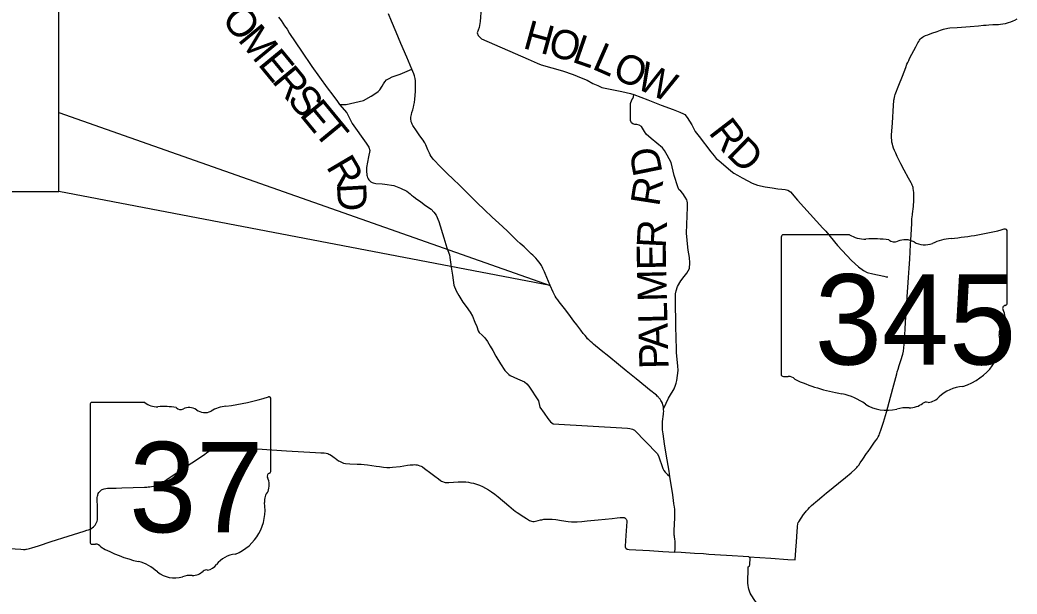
# Model space of a CAD drawing. Extents: x 1761803 to 2441803, y 509895 to 949895.
# Drawn here: x 2027446 to 2058182, y 720477 to 738164 of the extents above; entities that cross this region are included whole.
import ezdxf

# ---------------------------------------------------------------- set-up
doc = ezdxf.new("R2010")
doc.units = 0
for name, color, linetype in [('GM_X_County_Road', 7, 'Continuous'), ('GM_X_Minor_Lake', 7, 'Continuous'), ('GM_X_State_Location', 7, 'Continuous'), ('GM_X_Township_Road', 7, 'Continuous')]:
    doc.layers.add(name, color=color, linetype=linetype)

msp = doc.modelspace()

# ---------------------------------------------------------------- linework, layer by layer
at = {"layer": 'GM_X_County_Road'}
for points in [[(2041730, 739361), (2041632, 738116), (2041605, 737932), (2041538, 737768), (2041570, 737688), (2041675, 737580), (2043109, 736954), (2043389, 736833), (2043512, 736786), (2044171, 736592), (2044504, 736485), (2044750, 736378), (2044933, 736309), (2045105, 736208), (2045256, 736150), (2045388, 736083), (2046003, 735955), (2046269, 735900), (2046370, 735869), (2046797, 735702), (2047214, 735544), (2047581, 735403), (2047783, 735328), (2047898, 735274)], [(2035414, 738255), (2035501, 738148), (2035596, 737984), (2035680, 737882), (2035755, 737745), (2036124, 737202), (2036443, 736733), (2036915, 736075), (2037087, 735846), (2037232, 735654), (2037300, 735560)], [(2037300, 735560), (2037500, 735564), (2038033, 735683), (2038271, 735819), (2038358, 735867), (2038492, 735956), (2038538, 736014), (2038608, 736125), (2038650, 736200), (2038691, 736258), (2038745, 736316), (2038826, 736365), (2038923, 736408), (2039167, 736492), (2039528, 736644)], [(2047528, 726662), (2047552, 726701), (2047608, 726798), (2047658, 726912), (2047675, 726970), (2047691, 727054), (2047718, 727214), (2047732, 727362), (2047729, 727509), (2047688, 727904), (2047687, 728022), (2047668, 728719), (2047652, 729556), (2047656, 729722), (2047671, 729814), (2047713, 729950), (2047820, 730126), (2047916, 730265), (2047998, 730359), (2048085, 730509), (2048096, 730681), (2048086, 730841), (2048041, 731068), (2048030, 731166), (2047995, 731598), (2048027, 732395), (2048020, 732532), (2048012, 732586), (2048000, 732624), (2047951, 732707), (2047875, 732819), (2047818, 732889), (2047758, 732944), (2047728, 733028), (2047612, 733371), (2047523, 733775), (2047396, 733996), (2047319, 734143), (2047254, 734222), (2047080, 734371), (2046900, 734516), (2046748, 734641), (2046693, 734723), (2046601, 734886), (2046529, 734927), (2046462, 734942), (2046404, 734944), (2046334, 734959), (2046296, 734992), (2046267, 735067), (2046264, 735161), (2046271, 735595), (2046306, 735707), (2046334, 735749), (2046356, 735799), (2046370, 735869)], [(2037300, 735560), (2037521, 735302), (2037689, 734977), (2038118, 734365), (2038199, 734240), (2038227, 734139), (2038190, 733945), (2038126, 733614), (2038124, 733519), (2038135, 733384), (2038144, 733355), (2038156, 733314), (2038175, 733274), (2038199, 733237), (2038266, 733182), (2038304, 733161), (2038338, 733142), (2038375, 733131), (2038420, 733127), (2038613, 733118), (2038698, 733108), (2038972, 733064), (2039175, 732984), (2039369, 732885), (2039471, 732804), (2039517, 732767)], [(2047898, 735274), (2047899, 735273), (2047937, 735255), (2048014, 735157), (2048161, 734930), (2048258, 734730), (2048381, 734569), (2048743, 734101), (2048850, 733975), (2048910, 733900), (2048985, 733836), (2049356, 733521), (2049453, 733444), (2049569, 733378), (2049708, 733297), (2049880, 733206), (2050022, 733138), (2050183, 733071), (2050415, 733026), (2050633, 732996), (2050812, 732965), (2050936, 732952), (2051030, 732936), (2051116, 732924), (2051198, 732871), (2051414, 732616), (2052199, 731751), (2052283, 731655), (2052643, 731215), (2053074, 730757), (2053293, 730554), (2053444, 730445), (2053564, 730383), (2053737, 730338), (2054075, 730267), (2054152, 730255), (2054203, 730248)], [(2039517, 732767), (2039573, 732727), (2039640, 732675), (2039802, 732558), (2039951, 732451), (2040118, 732334), (2040208, 732239), (2040278, 732147), (2040363, 731950), (2040517, 731456), (2040602, 731142), (2040692, 730923), (2040737, 730547), (2040775, 730301), (2040820, 729991), (2040897, 729817), (2040970, 729671), (2041102, 729467), (2041204, 729336), (2041328, 729160), (2041396, 729040), (2041466, 728852), (2041531, 728715), (2041572, 728587), (2041598, 728534), (2041691, 728450), (2041778, 728366), (2041861, 728259), (2041945, 728118), (2042023, 727976), (2042119, 727808), (2042255, 727571), (2042396, 727363), (2042474, 727279), (2042516, 727246)], [(2042516, 727246), (2042555, 727215), (2042784, 727112), (2043001, 727010), (2043067, 726952), (2043128, 726877), (2043434, 726429), (2043473, 726239), (2043610, 726045), (2043723, 725884), (2043800, 725784), (2043882, 725723), (2046170, 725587), (2046245, 725580), (2046289, 725568), (2046333, 725553), (2046385, 725524), (2047089, 724802), (2047129, 724735), (2047261, 724343), (2047299, 724285), (2047332, 724227), (2047410, 724158), (2047483, 724097)], [(2047287, 726186), (2047362, 726359), (2047437, 726512), (2047528, 726662)]]:
    msp.add_lwpolyline(points, dxfattribs=at)
at = {"layer": 'GM_X_Minor_Lake'}
for points in [[(2047625, 722629), (2047634, 722826), (2047637, 722941), (2047635, 723003), (2047629, 723085), (2047622, 723160), (2047616, 723206), (2047606, 723268), (2047594, 723360), (2047567, 723533), (2047483, 724097), (2047457, 724261), (2047371, 724790), (2047319, 725107), (2047270, 725411), (2047254, 725536), (2047252, 725577), (2047250, 725621), (2047250, 725662), (2047250, 725705), (2047252, 725745), (2047256, 725793), (2047283, 726023), (2047286, 726058), (2047289, 726105), (2047288, 726160), (2047287, 726186), (2047280, 726247), (2047265, 726311), (2047248, 726356), (2047222, 726412), (2047202, 726445), (2047177, 726482), (2047153, 726511), (2047133, 726535), (2047115, 726552), (2047092, 726575), (2047063, 726600), (2046854, 726769), (2046733, 726869), (2046445, 727103), (2046136, 727355), (2045901, 727547), (2045599, 727794), (2045363, 727985), (2045130, 728172), (2045080, 728215), (2045033, 728258), (2044986, 728304), (2044946, 728345), (2044906, 728388), (2044865, 728438), (2044811, 728505), (2044738, 728603), (2044610, 728773), (2044521, 728889), (2044416, 729028), (2044330, 729142), (2044229, 729272), (2044150, 729375), (2044071, 729477), (2044025, 729540), (2043980, 729604), (2043945, 729659), (2043910, 729721), (2043881, 729780), (2043794, 729983), (2043691, 730230), (2043641, 730352), (2043619, 730404), (2043600, 730445), (2043569, 730510), (2043545, 730554), (2043522, 730595), (2043502, 730628), (2043477, 730665), (2043444, 730711), (2043401, 730763), (2043347, 730826), (2043306, 730867), (2043259, 730913), (2043206, 730963), (2043147, 731020), (2042985, 731170), (2042870, 731278), (2042778, 731364), (2042461, 731663), (2042206, 731901), (2042004, 732091), (2041770, 732311), (2041542, 732532), (2041315, 732755), (2041179, 732889), (2040981, 733083), (2040812, 733249), (2040610, 733447), (2040379, 733672), (2040222, 733831), (2040189, 733868), (2040159, 733906), (2040123, 733956), (2040094, 734008), (2040068, 734058), (2040039, 734118), (2040020, 734166), (2040001, 734214), (2039982, 734261), (2039955, 734320), (2039924, 734375), (2039902, 734411), (2039871, 734458), (2039775, 734594), (2039687, 734720), (2039647, 734778), (2039577, 734881), (2039556, 734915), (2039538, 734951), (2039523, 734986), (2039510, 735024), (2039501, 735059), (2039495, 735102), (2039495, 735137), (2039498, 735173), (2039505, 735212), (2039513, 735253), (2039528, 735308), (2039554, 735400), (2039576, 735481), (2039591, 735543), (2039604, 735619), (2039618, 735719), (2039636, 735963), (2039644, 736105), (2039644, 736157), (2039643, 736223), (2039638, 736288), (2039625, 736360), (2039605, 736441), (2039583, 736506), (2039556, 736575), (2039528, 736644), (2039369, 737021), (2039192, 737442), (2039046, 737789), (2038902, 738130), (2038807, 738356)], [(2054958, 732163), (2054962, 732196), (2054988, 732419), (2054993, 732486), (2054997, 732541), (2055002, 732647), (2055002, 732748), (2055000, 732849), (2054995, 732913), (2054985, 732971), (2054978, 733002), (2054967, 733035), (2054952, 733075), (2054936, 733109), (2054920, 733144), (2054837, 733289), (2054700, 733541), (2054600, 733728), (2054489, 733962), (2054441, 734065), (2054407, 734139), (2054378, 734211), (2054353, 734284), (2054338, 734333), (2054326, 734404), (2054318, 734469), (2054316, 734523), (2054316, 734611), (2054339, 734999), (2054371, 735525), (2054372, 735576), (2054381, 735633), (2054386, 735688), (2054390, 735727), (2054401, 735779), (2054413, 735830), (2054426, 735871), (2054537, 736159), (2054652, 736435), (2054752, 736703), (2054788, 736800), (2054813, 736858), (2054843, 736918), (2054869, 736975), (2054944, 737113), (2055063, 737334), (2055123, 737456), (2055151, 737504), (2055176, 737543), (2055197, 737571), (2055230, 737604), (2055267, 737634), (2055301, 737656), (2055364, 737684), (2055436, 737710), (2055560, 737755), (2055718, 737809), (2055823, 737846), (2055882, 737868), (2055918, 737880), (2055957, 737891), (2056004, 737903), (2056044, 737909), (2056111, 737919), (2056334, 737934), (2056739, 737966), (2056997, 737987), (2057144, 737999), (2057226, 738007), (2057314, 738014), (2057440, 738021), (2057550, 738027), (2057612, 738029), (2057676, 738032), (2057747, 738042), (2057822, 738056), (2057920, 738081), (2057992, 738107), (2058059, 738134), (2058113, 738160), (2058182, 738196)], [(2054779, 729374), (2054782, 729430), (2054797, 729641), (2054815, 729921), (2054833, 730225), (2054856, 730521), (2054877, 730797), (2054901, 731244), (2054920, 731542), (2054935, 731893), (2054940, 731971), (2054943, 732041), (2054958, 732163)], [(2053927, 725370), (2053927, 725371), (2053947, 725418), (2053994, 725552), (2054064, 725770), (2054161, 726081), (2054244, 726385), (2054353, 726807), (2054474, 727264), (2054489, 727320), (2054514, 727403), (2054549, 727515), (2054616, 727729), (2054640, 727804), (2054657, 727871), (2054679, 727961), (2054695, 728059), (2054705, 728165), (2054710, 728263), (2054746, 728848), (2054779, 729374)], [(2053544, 724802), (2053592, 724872), (2053660, 724970), (2053770, 725125), (2053823, 725199), (2053869, 725263), (2053902, 725320), (2053927, 725370)], [(2027648, 721857), (2027699, 721866), (2027736, 721876), (2027809, 721898), (2028014, 721963), (2028408, 722091), (2028937, 722259), (2029423, 722415), (2029507, 722440), (2029556, 722457), (2029607, 722476), (2029637, 722491), (2029673, 722513), (2029713, 722547), (2029743, 722578), (2029754, 722590), (2029762, 722601), (2029787, 722640), (2029807, 722680), (2029822, 722724), (2029832, 722765), (2029839, 722828), (2029839, 722910), (2029833, 723172), (2029831, 723376), (2029831, 723455), (2029836, 723493), (2029842, 723528), (2029860, 723572), (2029876, 723603), (2029894, 723627), (2029917, 723651), (2029940, 723672), (2029963, 723689), (2029985, 723701), (2030010, 723713), (2030042, 723723), (2030089, 723731), (2030149, 723735), (2030408, 723744), (2030586, 723751), (2031287, 723772), (2031355, 723773), (2031402, 723777), (2031451, 723782), (2031504, 723789), (2031568, 723802), (2031629, 723819), (2031694, 723843), (2031760, 723874), (2031836, 723915), (2031969, 724003), (2032385, 724280), (2033102, 724759), (2033240, 724854), (2033294, 724890), (2033348, 724923), (2033396, 724950), (2033448, 724973), (2033498, 724994), (2033557, 725011), (2033596, 725020), (2033637, 725027), (2033680, 725031), (2033718, 725033), (2033770, 725031), (2033857, 725025), (2034370, 724983), (2034757, 724952), (2035665, 724887), (2036558, 724840), (2036724, 724831), (2036782, 724828), (2036822, 724824), (2036886, 724813), (2036932, 724802), (2036965, 724790), (2037000, 724774), (2037046, 724748), (2037095, 724716), (2037135, 724687), (2037162, 724666), (2037270, 724586), (2037297, 724568), (2037338, 724547), (2037380, 724526), (2037421, 724513), (2037481, 724501), (2037616, 724492), (2037843, 724481), (2037965, 724474), (2038056, 724467), (2038155, 724456), (2038297, 724438), (2038429, 724419), (2038528, 724405), (2038648, 724389), (2038756, 724380), (2038849, 724377), (2038931, 724382), (2039170, 724411), (2039391, 724443), (2039472, 724454), (2039518, 724460), (2039570, 724463), (2039610, 724464), (2039649, 724462), (2039689, 724455), (2039721, 724449), (2039774, 724432), (2039816, 724413), (2039853, 724393), (2039918, 724350), (2040111, 724203), (2040236, 724106), (2040347, 724022), (2040411, 723976), (2040439, 723959), (2040476, 723941), (2040518, 723926), (2040552, 723918), (2040578, 723914), (2040600, 723913), (2040663, 723913), (2040959, 723931), (2041076, 723937), (2041136, 723936), (2041195, 723931), (2041270, 723922), (2041344, 723908), (2041431, 723888), (2041521, 723863), (2041609, 723832), (2041701, 723789), (2041795, 723741), (2041890, 723686), (2041984, 723628), (2042082, 723558), (2042184, 723474), (2042513, 723194), (2042660, 723071), (2042708, 723033), (2042769, 722992), (2042974, 722857), (2043059, 722802), (2043119, 722762), (2043150, 722743), (2043185, 722730), (2043219, 722720), (2043259, 722715), (2043295, 722714), (2043337, 722719), (2043421, 722740), (2043496, 722760), (2043530, 722768), (2043595, 722780), (2043610, 722782)], [(2053425, 724628), (2053544, 724802)], [(2053240, 724372), (2053243, 724376), (2053268, 724404), (2053302, 724450), (2053349, 724516), (2053425, 724628)], [(2051907, 723256), (2051979, 723318), (2052028, 723359), (2052163, 723474), (2052312, 723594), (2052450, 723705), (2052516, 723758), (2052675, 723890), (2052890, 724067), (2053069, 724216), (2053193, 724324), (2053215, 724347), (2053240, 724372)], [(2051423, 722629), (2051427, 722643), (2051439, 722681), (2051451, 722705), (2051601, 722923), (2051657, 722999), (2051685, 723034), (2051713, 723066), (2051742, 723097), (2051785, 723144), (2051846, 723200), (2051907, 723256)], [(2043610, 722782), (2043645, 722786), (2043710, 722789), (2043795, 722787), (2043856, 722782), (2043965, 722769), (2044142, 722745), (2044345, 722717), (2044449, 722705), (2044528, 722700), (2044625, 722699), (2044763, 722709), (2044929, 722728), (2045270, 722763), (2045706, 722807), (2045852, 722822), (2045952, 722832), (2045998, 722835), (2046031, 722836), (2046033, 722836)], [(2046033, 722836), (2046051, 722835), (2046065, 722833), (2046075, 722831), (2046085, 722827), (2046102, 722820), (2046117, 722809), (2046127, 722797), (2046136, 722783), (2046143, 722766), (2046151, 722741), (2046152, 722716), (2046143, 722567), (2046126, 722276), (2046105, 721954), (2046106, 721927), (2046107, 721916), (2046110, 721908), (2046114, 721898), (2046119, 721888), (2046127, 721878)], [(2047632, 721764), (2047639, 721877), (2047642, 721919), (2047645, 721969), (2047646, 722021), (2047643, 722064), (2047640, 722095), (2047631, 722173), (2047624, 722225), (2047620, 722257), (2047617, 722293), (2047617, 722440), (2047624, 722624), (2047625, 722629)], [(2051345, 721530), (2051368, 721832), (2051387, 722082), (2051402, 722403), (2051411, 722536), (2051415, 722576), (2051421, 722620), (2051423, 722629)], [(2026438, 721934), (2026445, 721933), (2026898, 721901), (2027300, 721871), (2027471, 721859), (2027556, 721854), (2027603, 721854), (2027642, 721856), (2027648, 721857)], [(2046127, 721878), (2046141, 721870), (2046156, 721864), (2046182, 721858), (2046221, 721854), (2046854, 721814), (2047260, 721788), (2047632, 721764)], [(2048520, 721712), (2048243, 721730), (2047827, 721754), (2047632, 721764)], [(2049912, 721622), (2049221, 721665), (2048686, 721700), (2048520, 721712)], [(2049896, 721267), (2049898, 721318), (2049919, 721327), (2049932, 721339), (2049936, 721352), (2049942, 721378), (2049954, 721588), (2049950, 721596), (2049939, 721608), (2049912, 721622)], [(2049912, 721622), (2050596, 721578), (2051118, 721544), (2051345, 721530)], [(2049883, 720948), (2049892, 721164), (2049896, 721267)], [(2050315, 719973), (2050284, 720016), (2050060, 720341), (2050023, 720395), (2049987, 720454), (2049960, 720508), (2049934, 720566), (2049913, 720624), (2049900, 720680), (2049890, 720741), (2049883, 720808), (2049883, 720948)]]:
    msp.add_lwpolyline(points, dxfattribs=at)
at = {"layer": 'GM_X_State_Location'}
for points in [[(1999264, 732882), (2028640, 732882), (2028640, 747716), (1999264, 747716)], [(2043794, 729983), (2028640, 732882), (2028640, 735317)]]:
    msp.add_lwpolyline(points, close=True, dxfattribs=at)
at = {"layer": 'GM_X_Township_Road'}
for p, q in [((2053022, 731548), (2050983, 731548)), ((2057876, 729442), (2057876, 731653)), ((2050915, 731476), (2050915, 727249)), ((2057875, 729443), (2057876, 729442)), ((2031295, 726382), (2029664, 726382)), ((2035178, 724276), (2035178, 726486)), ((2029609, 726309), (2029609, 722082)), ((2035178, 724276), (2035178, 724276))]:
    msp.add_line(p, q, dxfattribs=at)
for centre, radius, start, end in [((2029673, 726318), 64.5, 98.1301, 188.1301), ((2031683, 726872), 626, 231.6195, 271.1119), ((2033194, 732144), 5905, 275.8445, 288.9065), ((2035116, 726496), 62, 351.8621, 97.738), ((2031891, 724009), 2246, 80.4867, 94.9883), ((2032401, 726340), 181, 219.7921, 297.1024), ((2032666, 725851), 375, 54.4667, 119.1411), ((2033150, 726521), 452, 233.8562, 294.8282), ((2033948, 725091), 1188, 97.3462, 120.7689), ((2035164, 724113), 95.9, 107.944, 210.337), ((2035112, 724267), 66.3, 289.6038, 7.7341), ((2034553, 723834), 576, 340.033, 23.6496), ((2035400, 723350), 419, 136.8065, 186.9296), ((2033525, 723069), 1477, 292.3089, 8.9858), ((2029674, 722073), 65.1, 171.9584, 258.3066), ((2029684, 722506), 497, 267.339, 280.6039), ((2029785, 721839), 179, 29.7484, 93.2717), ((2032046, 725636), 4265, 240.4129, 257.1985), ((2034148, 720896), 809, 94.4031, 142.5768), ((2030775, 720184), 1334, 47.1842, 75.836), ((2032218, 721818), 847, 230.7004, 286.2918), ((2032769, 721501), 451, 268.777, 315.5493), ((2033177, 721092), 127, 65.7517, 132.6484), ((2033123, 721673), 477, 282.8732, 323.2771), ((2032707, 720356), 696, 85.6951, 111.2099)]:
    msp.add_arc(centre, radius, start, end, dxfattribs=at)
for centre, major_axis, start_param, end_param in [((2050995, 731485), (80.6, 0), 1.712693, 3.28349), ((2053507, 732039), (782, 0), 4.042523, 4.731795), ((2055396, 737311), (7382, 0), 4.814394, 5.042369), ((2057799, 731662), (77.5, 0), 6.141152, 7.989035), ((2053767, 729175), (2808, 0), 1.404758, 1.657858), ((2054404, 731506), (226, 0), 3.836095, 5.185415), ((2054736, 731018), (469, 0), 0.950623, 2.079405), ((2055341, 731688), (564, 0), 4.081561, 5.145723), ((2056338, 730257), (1485, 0), 1.699011, 2.107814), ((2057793, 729434), (82.9, 0), 5.05454, 6.418171), ((2057858, 729280), (120, 0), 1.883978, 3.671073), ((2057095, 729000), (720, 0), 5.934695, 6.695948), ((2058153, 728517), (524, 0), 2.387724, 3.262537), ((2055810, 728236), (1846, 0), 5.101752, 6.440018), ((2050995, 727240), (81.4, 0), 3.00124, 4.508301), ((2051008, 727672), (621, 0), 4.665946, 4.897461), ((2051135, 727005), (224, 0), 0.519207, 1.627899), ((2053961, 730803), (5331, 0), 4.195997, 4.488961), ((2052372, 725350), (1668, 0), 0.823519, 1.323587), ((2056588, 726062), (1011, 0), 1.647645, 2.488434), ((2054176, 726984), (1058, 0), 4.026481, 4.996735), ((2054865, 726668), (564, 0), 4.691044, 5.507374), ((2055375, 726258), (159, 0), 1.147584, 2.315152), ((2055307, 726839), (597, 0), 4.937069, 5.64225), ((2054787, 725523), (870, 0), 1.495662, 1.94098)]:
    msp.add_ellipse(centre, major_axis=major_axis, ratio=0.8, start_param=start_param, end_param=end_param, dxfattribs=at)

# ---------------------------------------------------------------- texts
at = {"layer": 'GM_X_County_Road'}
for s, rotation, p in [('O', 308.7423, (2033633, 738176)), ('M', 309.4743, (2034137, 737549)), ('H', 344.5912, (2042918, 737304)), ('O', 344.4568, (2043681, 737094)), ('L', 340.8575, (2044430, 736886)), ('L', 336.2958, (2045048, 736672)), ('E', 309.4771, (2034758, 736795)), ('O', 336.0342, (2045664, 736402)), ('R', 309.4742, (2035186, 736275)), ('W', 336.0307, (2046387, 736080)), ('S', 309.4736, (2035656, 735705)), ('E', 309.4739, (2036042, 735236)), ('T', 309.4739, (2036470, 734716)), ('R', 307.5522, (2048650, 734692)), ('D', 315.7616, (2049192, 734003)), ('R', 300.518, (2036870, 733645)), ('D', 101.4832, (2047259, 733467)), ('R', 81.0612, (2047151, 732394)), ('D', 273.2255, (2037213, 733115)), ('R', 87.0988, (2047353, 731122)), ('E', 91.11, (2047367, 730466)), ('M', 91.4149, (2047391, 729491)), ('L', 91.4187, (2047407, 728818)), ('A', 91.4236, (2047427, 728026)), ('P', 91.4208, (2047442, 727419))]:
    msp.add_text(s, height=900, rotation=rotation, dxfattribs=at).set_placement(p)
at = {"layer": 'GM_X_Township_Road'}
for s, p in [('345', (2051944, 727547)), ('37', (2030811, 722381))]:
    msp.add_text(s, height=2784.4, dxfattribs=at).set_placement(p)

doc.saveas('drawing.dxf')
